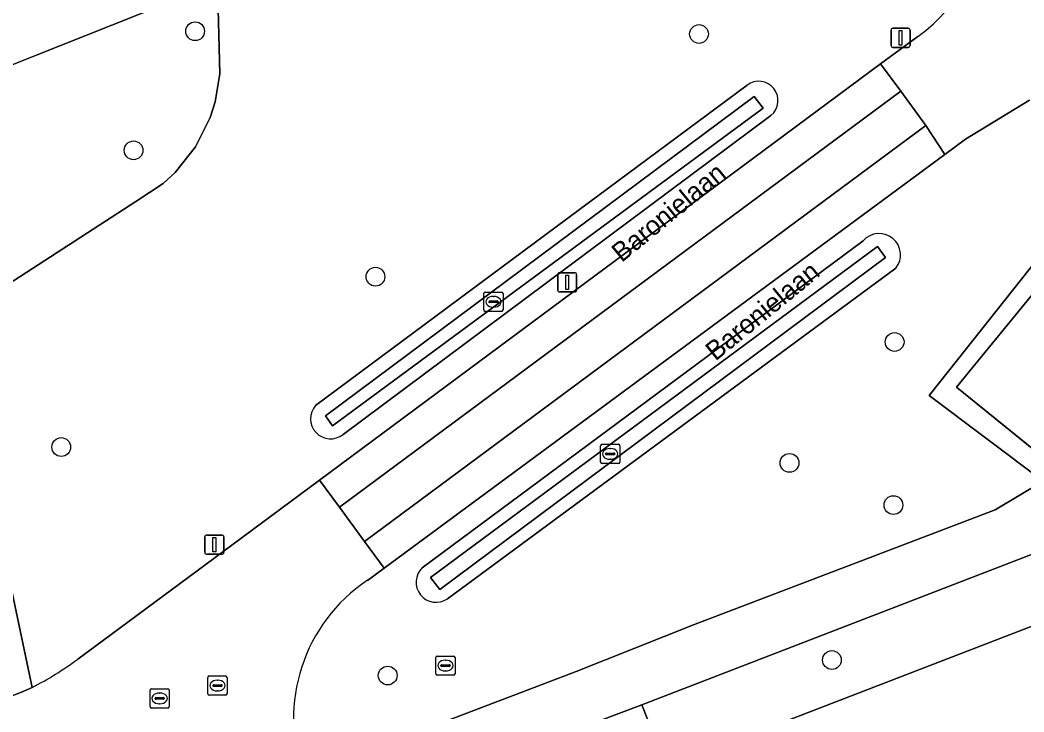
# Model space of a CAD drawing. Extents: x 159680 to 160786, y 387323 to 388340.
# Drawn here: x 160115.9 to 160168.3, y 387981.6 to 388017.7 of the extents above; entities that cross this region are included whole.
import ezdxf

# ---------------------------------------------------------------- set-up
doc = ezdxf.new("R2010")
doc.units = 0
for name, color, linetype in [('IMGEO_Boom', 7, 'Continuous'), ('IMGEO_Greppel_droge_sloot', 7, 'Continuous'), ('IMGEO_Groenvoorziening', 7, 'Continuous'), ('IMGEO_Hek', 7, 'Continuous'), ('IMGEO_Kolk', 7, 'Continuous'), ('IMGEO_Lichtmast', 7, 'Continuous'), ('IMGEO_Oever', 7, 'Continuous'), ('IMGEO_Openbare_ruimte_label', 7, 'Continuous'), ('IMGEO_Rijbaan_lokaal_gesloten', 7, 'Continuous'), ('IMGEO_Rijbaan_lokaal_open', 7, 'Continuous'), ('IMGEO_Rioolput', 7, 'Continuous'), ('IMGEO_Voetpad_halfverhard', 7, 'Continuous'), ('IMGEO_Voetpad_open', 7, 'Continuous')]:
    doc.layers.add(name, color=color, linetype=linetype)

msp = doc.modelspace()

# ---------------------------------------------------------------- linework, layer by layer
at = {"layer": 'IMGEO_Boom'}
for centre in [(160125.059, 388017.13), (160151.34, 388016.988), (160121.849, 388010.923), (160134.465, 388004.336), (160161.542, 388000.932), (160118.077, 387995.456), (160156.06, 387994.63), (160161.48, 387992.432), (160158.273, 387984.354), (160135.103, 387983.546)]:
    msp.add_circle(centre, 0.489, dxfattribs=at)
at = {"layer": 'IMGEO_Greppel_droge_sloot'}
for points in [[(160131.863, 387997.08), (160132.222, 387996.559), (160154.677, 388013.125), (160154.222, 388013.732)], [(160161.064, 388005.344), (160160.652, 388005.915), (160137.331, 387988.662), (160137.818, 387988.027)]]:
    msp.add_lwpolyline(points, close=True, dxfattribs=at)
at = {"layer": 'IMGEO_Groenvoorziening'}
for points in [[(160166.125, 388024.041), (160165.275, 388032.47), (160165.059, 388035.262), (160160.372, 388033.273), (160155.987, 388031.524), (160126.23, 388019.656), (160126.344, 388014.91), (160126.103, 388013.446), (160125.846, 388012.631), (160125.083, 388011.106), (160124.02, 388009.772), (160123.39, 388009.196), (160121.967, 388008.256), (160112.76, 388002.304), (160112.774, 388002.223), (160113.928, 387995.528), (160114.105, 387994.618), (160114.502, 387992.58), (160116.567, 387982.928)], [(160125.846, 388012.631), (160126.103, 388013.446), (160126.344, 388014.91), (160126.23, 388019.656), (160116.649, 388015.835), (160114.456, 388014.96), (160114.154, 388014.758), (160113.722, 388014.469), (160111.987, 388013.468)], [(160160.812, 388015.433), (160162.749, 388016.86)], [(160118.934, 387984.392), (160126.043, 387989.654), (160131.544, 387993.725), (160160.812, 388015.433)], [(160145.042, 388007.789), (160153.852, 388014.325)], [(160168.572, 388013.533), (160165.236, 388011.499), (160164.163, 388010.707), (160134.923, 387989.142), (160134.042, 387988.508)], [(160163.337, 387998.137), (160164.817, 388000), (160172.298, 388009.417), (160179.067, 388004.335), (160179.091, 388004.369), (160181.002, 388007.834), (160181.761, 388009.621), (160182.319, 388011.579), (160183.007, 388013.607)], [(160111.224, 388011.36), (160112.76, 388002.304), (160121.967, 388008.256), (160123.39, 388009.196), (160124.02, 388009.772), (160125.083, 388011.106), (160125.846, 388012.631)], [(160155.092, 388012.741), (160132.773, 387996.111)], [(160131.344, 387997.627), (160145.042, 388007.789)], [(160136.908, 387989.163), (160159.897, 388006.203)], [(160161.613, 388004.778), (160138.215, 387987.548)], [(160207.556, 387953.24), (160205.296, 387988.427), (160196.008, 387988.241), (160194.379, 387994.988), (160200.5, 387996.578), (160204.723, 387997.367), (160204.554, 388000), (160204.497, 388000.886), (160199.753, 388000), (160193.558, 387998.39), (160191.271, 387997.796), (160189.054, 387997.22), (160177.598, 387993.294), (160148.364, 387982.025), (160149.641, 387978.766), (160178.798, 387990.005), (160187.566, 387993.01), (160192.055, 387994.383), (160193.584, 387987.727), (160185.705, 387985.65), (160177.161, 387982.262), (160177.993, 387979.097)], [(160130.712, 387978.33), (160138.132, 387981.171), (160144.936, 387983.757), (160151.053, 387986.18), (160166.782, 387992.187), (160169.286, 387993.671), (160163.337, 387998.137)]]:
    msp.add_lwpolyline(points, dxfattribs=at)
for points in [[(160164.77, 387998.586), (160165.929, 388000), (160169.168, 388003.949), (160172.564, 388008.09), (160177.63, 388003.943), (160174.171, 388000), (160171.033, 387996.424), (160171.901, 387995.677), (160173.796, 387997.437), (160176.416, 388000.66), (160179.067, 388004.335), (160172.298, 388009.417), (160164.817, 388000), (160163.337, 387998.137), (160169.286, 387993.671), (160170.183, 387994.202)], [(160169.168, 388003.949), (160165.929, 388000), (160164.77, 387998.586), (160170.183, 387994.202), (160171.901, 387995.677), (160171.033, 387996.424), (160174.171, 388000)], [(160177.161, 387982.262), (160185.705, 387985.65), (160193.584, 387987.727), (160192.055, 387994.383), (160187.566, 387993.01), (160178.798, 387990.005), (160149.641, 387978.766), (160152.156, 387972.348)]]:
    msp.add_lwpolyline(points, close=True, dxfattribs=at)
for centre, radius, start, end in [((160158.173, 388023.395), 7.978, 304.9987, 4.6421), ((160154.455, 388013.52), 1.006, 309.2647, 126.845), ((160160.736, 388005.468), 1.116, 321.7912, 138.795), ((160132.125, 387996.932), 1.046, 138.3479, 308.2678), ((160137.625, 387988.407), 1.042, 133.495, 304.4706), ((160138.876, 387981.293), 8.685, 123.8192, 199.9471), ((160108.309, 387998.924), 18.002, 297.3035, 306.1705)]:
    msp.add_arc(centre, radius, start, end, dxfattribs=at)
at = {"layer": 'IMGEO_Hek'}
msp.add_lwpolyline([(160170.41, 387994.018), (160164.77, 387998.586), (160165.929, 388000), (160169.168, 388003.949), (160172.564, 388008.09), (160177.63, 388003.943), (160174.171, 388000), (160171.033, 387996.424), (160172.174, 387995.442)], dxfattribs=at)
at = {"layer": 'IMGEO_Kolk'}
for p, q in [((160140.193, 388003.528), (160141.045, 388003.528)), ((160140.118, 388002.602), (160140.118, 388003.454)), ((160140.377, 388003.022), (160140.377, 388003.034)), ((160140.42, 388003.071), (160140.818, 388003.071)), ((160140.606, 388003.308), (160140.631, 388003.308)), ((160140.861, 388003.034), (160140.861, 388003.022)), ((160141.119, 388003.454), (160141.119, 388002.602)), ((160141.045, 388002.528), (160140.193, 388002.528)), ((160140.815, 388002.985), (160140.417, 388002.985)), ((160140.629, 388002.748), (160140.604, 388002.748)), ((160146.206, 387994.673), (160146.206, 387995.525)), ((160146.281, 387995.599), (160147.133, 387995.599)), ((160146.508, 387995.142), (160146.906, 387995.142)), ((160146.694, 387995.379), (160146.719, 387995.379)), ((160147.207, 387995.525), (160147.207, 387994.673)), ((160146.465, 387995.093), (160146.465, 387995.105)), ((160146.903, 387995.056), (160146.505, 387995.056)), ((160146.717, 387994.819), (160146.692, 387994.819)), ((160146.949, 387995.105), (160146.949, 387995.093)), ((160147.133, 387994.599), (160146.281, 387994.599)), ((160137.614, 387983.637), (160137.614, 387984.489)), ((160137.689, 387984.563), (160138.541, 387984.563)), ((160138.102, 387984.343), (160138.127, 387984.343)), ((160138.615, 387984.489), (160138.615, 387983.637)), ((160137.873, 387984.057), (160137.873, 387984.069)), ((160138.311, 387984.02), (160137.913, 387984.02)), ((160137.916, 387984.106), (160138.314, 387984.106)), ((160138.125, 387983.783), (160138.1, 387983.783)), ((160138.357, 387984.069), (160138.357, 387984.057)), ((160138.541, 387983.563), (160137.689, 387983.563))]:
    msp.add_line(p, q, dxfattribs=at)
for points in [[(160140.193, 388003.528), (160141.045, 388003.528)], [(160140.118, 388002.602), (160140.118, 388003.454)], [(160141.119, 388003.454), (160141.119, 388002.602)], [(160141.045, 388002.528), (160140.193, 388002.528)], [(160146.206, 387994.673), (160146.206, 387995.525)], [(160146.281, 387995.599), (160147.133, 387995.599)], [(160147.207, 387995.525), (160147.207, 387994.673)], [(160147.133, 387994.599), (160146.281, 387994.599)], [(160137.614, 387983.637), (160137.614, 387984.489)], [(160137.689, 387984.563), (160138.541, 387984.563)], [(160138.615, 387984.489), (160138.615, 387983.637)], [(160138.541, 387983.563), (160137.689, 387983.563)]]:
    msp.add_lwpolyline(points, dxfattribs=at)
for centre, radius, start, end in [((160140.195, 388003.452), 0.0765, 91.552, 178.448), ((160140.195, 388003.452), 0.0765, 91.552, 178.448), ((160141.043, 388003.452), 0.0765, 1.552, 88.448), ((160141.043, 388003.452), 0.0765, 1.552, 88.448), ((160140.417, 388003.031), 0.0403, 85.8775, 175.7526), ((160140.414, 388003.021), 0.0366, 178.938, 274.7102), ((160140.818, 388003.028), 0.043, 264.8664, 352.4533), ((160140.822, 388003.033), 0.0386, 1.7309, 96.639), ((160140.195, 388002.604), 0.0765, 181.552, 268.448), ((160140.195, 388002.604), 0.0765, 181.552, 268.448), ((160141.043, 388002.604), 0.0765, 271.552, 358.448), ((160141.043, 388002.604), 0.0765, 271.552, 358.448), ((160146.283, 387995.523), 0.0765, 91.552, 178.448), ((160146.283, 387995.523), 0.0765, 91.552, 178.448), ((160146.505, 387995.102), 0.0403, 85.8775, 175.7526), ((160146.91, 387995.104), 0.0386, 1.7309, 96.639), ((160147.131, 387995.523), 0.0765, 1.552, 88.448), ((160147.131, 387995.523), 0.0765, 1.552, 88.448), ((160146.283, 387994.675), 0.0765, 181.552, 268.448), ((160146.283, 387994.675), 0.0765, 181.552, 268.448), ((160146.502, 387995.092), 0.0366, 178.938, 274.7102), ((160146.906, 387995.099), 0.043, 264.8664, 352.4533), ((160147.131, 387994.675), 0.0765, 271.552, 358.448), ((160147.131, 387994.675), 0.0765, 271.552, 358.448), ((160137.691, 387984.487), 0.0765, 91.552, 178.448), ((160137.691, 387984.487), 0.0765, 91.552, 178.448), ((160138.539, 387984.487), 0.0765, 1.552, 88.448), ((160138.539, 387984.487), 0.0765, 1.552, 88.448), ((160137.691, 387983.639), 0.0765, 181.552, 268.448), ((160137.691, 387983.639), 0.0765, 181.552, 268.448), ((160137.913, 387984.066), 0.0403, 85.8775, 175.7526), ((160137.91, 387984.056), 0.0366, 178.938, 274.7102), ((160138.314, 387984.063), 0.043, 264.8664, 352.4533), ((160138.318, 387984.068), 0.0386, 1.7309, 96.639), ((160138.539, 387983.639), 0.0765, 271.552, 358.448), ((160138.539, 387983.639), 0.0765, 271.552, 358.448)]:
    msp.add_arc(centre, radius, start, end, dxfattribs=at)
for centre, major_axis, ratio, start_param, end_param in [((160140.605, 388003.028), (-0.387, 0.002), 0.722429, 4.712389, 7.853982), ((160140.63, 388003.028), (-0.39, 0.002), 0.717154, 1.570796, 4.712389), ((160146.693, 387995.099), (-0.387, 0.002), 0.722429, 4.712389, 7.853982), ((160146.718, 387995.099), (-0.39, 0.002), 0.717154, 1.570796, 4.712389), ((160138.101, 387984.063), (-0.387, 0.002), 0.722429, 4.712389, 7.853982), ((160138.126, 387984.063), (-0.39, 0.002), 0.717154, 1.570796, 4.712389)]:
    msp.add_ellipse(centre, major_axis=major_axis, ratio=ratio, start_param=start_param, end_param=end_param, dxfattribs=at)
at = {"layer": 'IMGEO_Lichtmast'}
for p, q in [((160161.354, 388016.388), (160161.354, 388017.188)), ((160161.354, 388017.188), (160161.354, 388016.388)), ((160161.454, 388017.288), (160162.244, 388017.288)), ((160162.244, 388017.288), (160161.454, 388017.288)), ((160162.344, 388017.188), (160162.344, 388016.388)), ((160162.344, 388016.388), (160162.344, 388017.188)), ((160162.244, 388016.288), (160161.454, 388016.288)), ((160161.454, 388016.288), (160162.244, 388016.288)), ((160143.968, 388003.641), (160143.968, 388004.441)), ((160143.968, 388004.441), (160143.968, 388003.641)), ((160144.068, 388004.541), (160144.858, 388004.541)), ((160144.858, 388004.541), (160144.068, 388004.541)), ((160144.958, 388004.441), (160144.958, 388003.641)), ((160144.958, 388003.641), (160144.958, 388004.441)), ((160144.858, 388003.541), (160144.068, 388003.541)), ((160144.068, 388003.541), (160144.858, 388003.541)), ((160125.566, 387989.968), (160125.566, 387990.768)), ((160125.566, 387990.768), (160125.566, 387989.968)), ((160125.666, 387990.868), (160126.456, 387990.868)), ((160126.456, 387990.868), (160125.666, 387990.868)), ((160126.556, 387990.768), (160126.556, 387989.968)), ((160126.556, 387989.968), (160126.556, 387990.768)), ((160126.456, 387989.868), (160125.666, 387989.868)), ((160125.666, 387989.868), (160126.456, 387989.868))]:
    msp.add_line(p, q, dxfattribs=at)
for points in [[(160161.774, 388017.163), (160161.924, 388017.163), (160161.924, 388016.413), (160161.774, 388016.413), (160161.774, 388017.163)], [(160144.388, 388004.416), (160144.538, 388004.416), (160144.538, 388003.666), (160144.388, 388003.666), (160144.388, 388004.416)], [(160125.986, 387990.743), (160126.136, 387990.743), (160126.136, 387989.993), (160125.986, 387989.993), (160125.986, 387990.743)]]:
    msp.add_lwpolyline(points, dxfattribs=at)
for centre, start, end in [((160161.454, 388017.188), 90, 180), ((160161.454, 388017.188), 90, 180), ((160162.244, 388017.188), 0, 90), ((160162.244, 388017.188), 360, 90), ((160161.454, 388016.388), 180, 270), ((160161.454, 388016.388), 180, 270), ((160162.244, 388016.388), 270, 0), ((160162.244, 388016.388), 270, 0), ((160144.068, 388004.441), 90, 180), ((160144.068, 388004.441), 90, 180), ((160144.858, 388004.441), 0, 90), ((160144.858, 388004.441), 360, 90), ((160144.068, 388003.641), 180, 270), ((160144.068, 388003.641), 180, 270), ((160144.858, 388003.641), 270, 0), ((160144.858, 388003.641), 270, 0), ((160125.666, 387990.768), 90, 180), ((160125.666, 387990.768), 90, 180), ((160126.456, 387990.768), 0, 90), ((160126.456, 387990.768), 360, 90), ((160125.666, 387989.968), 180, 270), ((160125.666, 387989.968), 180, 270), ((160126.456, 387989.968), 270, 0), ((160126.456, 387989.968), 270, 0)]:
    msp.add_arc(centre, 0.1, start, end, dxfattribs=at)
at = {"layer": 'IMGEO_Oever'}
for points in [[(160153.852, 388014.325), (160145.042, 388007.789), (160131.344, 387997.627)], [(160132.773, 387996.111), (160155.092, 388012.741)], [(160159.897, 388006.203), (160136.908, 387989.163)], [(160138.215, 387987.548), (160161.613, 388004.778)]]:
    msp.add_lwpolyline(points, dxfattribs=at)
for points in [[(160131.863, 387997.08), (160154.222, 388013.732), (160154.677, 388013.125), (160132.222, 387996.559)], [(160161.064, 388005.344), (160137.818, 387988.027), (160137.331, 387988.662), (160160.652, 388005.915)]]:
    msp.add_lwpolyline(points, close=True, dxfattribs=at)
for centre, radius, start, end in [((160154.455, 388013.52), 1.006, 309.2647, 126.845), ((160160.736, 388005.468), 1.116, 321.7912, 138.795), ((160132.125, 387996.932), 1.046, 138.3479, 308.2678), ((160137.625, 387988.407), 1.042, 133.495, 304.4706)]:
    msp.add_arc(centre, radius, start, end, dxfattribs=at)
at = {"layer": 'IMGEO_Rijbaan_lokaal_gesloten'}
for points in [[(160161.866, 388014.009), (160160.812, 388015.433), (160131.544, 387993.725), (160132.587, 387992.324)], [(160164.163, 388010.707), (160163.173, 388012.216), (160133.898, 387990.541), (160134.923, 387989.142)]]:
    msp.add_lwpolyline(points, close=True, dxfattribs=at)
at = {"layer": 'IMGEO_Rijbaan_lokaal_open'}
for points in [[(160162.749, 388016.86), (160160.812, 388015.433), (160161.866, 388014.009), (160163.173, 388012.216), (160164.163, 388010.707), (160165.236, 388011.499), (160168.572, 388013.533)], [(160134.042, 387988.508), (160134.923, 387989.142), (160133.898, 387990.541), (160132.587, 387992.324), (160131.544, 387993.725), (160126.043, 387989.654), (160118.934, 387984.392)], [(160116.567, 387982.928), (160116.007, 387982.686), (160114.953, 387982.272), (160114.267, 387981.984), (160113.681, 387981.763), (160114.307, 387980.164), (160115.127, 387978.084), (160115.759, 387976.477), (160116.703, 387976.841)]]:
    msp.add_lwpolyline(points, dxfattribs=at)
msp.add_lwpolyline([(160163.173, 388012.216), (160161.866, 388014.009), (160132.587, 387992.324), (160133.898, 387990.541)], close=True, dxfattribs=at)
for centre, radius, start, end in [((160158.173, 388023.395), 7.978, 304.9987, 4.6421), ((160138.876, 387981.293), 8.685, 123.8192, 199.9471), ((160108.309, 387998.924), 18.002, 297.3035, 306.1705)]:
    msp.add_arc(centre, radius, start, end, dxfattribs=at)
at = {"layer": 'IMGEO_Rioolput'}
for p, q in [((160125.725, 387982.599), (160125.725, 387983.451)), ((160125.8, 387983.525), (160126.652, 387983.525)), ((160126.213, 387983.305), (160126.238, 387983.305)), ((160126.726, 387983.451), (160126.726, 387982.599)), ((160122.708, 387981.927), (160122.708, 387982.779)), ((160122.783, 387982.853), (160123.635, 387982.853)), ((160123.196, 387982.633), (160123.221, 387982.633)), ((160123.709, 387982.779), (160123.709, 387981.927)), ((160125.984, 387983.019), (160125.984, 387983.031)), ((160126.422, 387982.982), (160126.024, 387982.982)), ((160126.027, 387983.068), (160126.425, 387983.068)), ((160126.236, 387982.745), (160126.211, 387982.745)), ((160126.468, 387983.031), (160126.468, 387983.019)), ((160122.967, 387982.347), (160122.967, 387982.359)), ((160123.405, 387982.31), (160123.007, 387982.31)), ((160123.01, 387982.396), (160123.408, 387982.396)), ((160123.219, 387982.073), (160123.194, 387982.073)), ((160123.451, 387982.359), (160123.451, 387982.347)), ((160126.652, 387982.525), (160125.8, 387982.525)), ((160123.635, 387981.853), (160122.783, 387981.853))]:
    msp.add_line(p, q, dxfattribs=at)
for points in [[(160125.725, 387982.599), (160125.725, 387983.451)], [(160125.8, 387983.525), (160126.652, 387983.525)], [(160126.726, 387983.451), (160126.726, 387982.599)], [(160122.708, 387981.927), (160122.708, 387982.779)], [(160122.783, 387982.853), (160123.635, 387982.853)], [(160123.709, 387982.779), (160123.709, 387981.927)], [(160126.652, 387982.525), (160125.8, 387982.525)], [(160123.635, 387981.853), (160122.783, 387981.853)]]:
    msp.add_lwpolyline(points, dxfattribs=at)
for centre, radius, start, end in [((160125.802, 387983.449), 0.0765, 91.552, 178.448), ((160125.802, 387983.449), 0.0765, 91.552, 178.448), ((160126.65, 387983.449), 0.0765, 1.552, 88.448), ((160126.65, 387983.449), 0.0765, 1.552, 88.448), ((160122.785, 387982.777), 0.0765, 91.552, 178.448), ((160122.785, 387982.777), 0.0765, 91.552, 178.448), ((160123.633, 387982.777), 0.0765, 1.552, 88.448), ((160123.633, 387982.777), 0.0765, 1.552, 88.448), ((160125.802, 387982.601), 0.0765, 181.552, 268.448), ((160125.802, 387982.601), 0.0765, 181.552, 268.448), ((160126.024, 387983.028), 0.0403, 85.8775, 175.7526), ((160126.021, 387983.018), 0.0366, 178.938, 274.7102), ((160126.425, 387983.025), 0.043, 264.8664, 352.4533), ((160126.429, 387983.03), 0.0386, 1.7309, 96.639), ((160126.65, 387982.601), 0.0765, 271.552, 358.448), ((160126.65, 387982.601), 0.0765, 271.552, 358.448), ((160123.007, 387982.356), 0.0403, 85.8775, 175.7526), ((160123.004, 387982.346), 0.0366, 178.938, 274.7102), ((160123.408, 387982.353), 0.043, 264.8664, 352.4533), ((160123.412, 387982.358), 0.0386, 1.7309, 96.639), ((160122.785, 387981.929), 0.0765, 181.552, 268.448), ((160122.785, 387981.929), 0.0765, 181.552, 268.448), ((160123.633, 387981.929), 0.0765, 271.552, 358.448), ((160123.633, 387981.929), 0.0765, 271.552, 358.448)]:
    msp.add_arc(centre, radius, start, end, dxfattribs=at)
for centre, major_axis, ratio, start_param, end_param in [((160126.212, 387983.025), (-0.387, 0.002), 0.722429, 4.712389, 7.853982), ((160126.237, 387983.025), (-0.39, 0.002), 0.717154, 1.570796, 4.712389), ((160123.195, 387982.353), (-0.387, 0.002), 0.722429, 4.712389, 7.853982), ((160123.22, 387982.353), (-0.39, 0.002), 0.717154, 1.570796, 4.712389)]:
    msp.add_ellipse(centre, major_axis=major_axis, ratio=ratio, start_param=start_param, end_param=end_param, dxfattribs=at)
at = {"layer": 'IMGEO_Voetpad_halfverhard'}
msp.add_lwpolyline([(160167.999, 387931.913), (160164.121, 387941.81), (160163.813, 387942.595), (160163.17, 387944.237), (160152.156, 387972.348), (160149.641, 387978.766), (160148.364, 387982.025), (160146.101, 387981.164), (160161.804, 387940.861), (160165.633, 387931.034)], dxfattribs=at)
at = {"layer": 'IMGEO_Voetpad_open'}
for points in [[(160111.987, 388013.468), (160113.722, 388014.469), (160114.154, 388014.758), (160114.456, 388014.96), (160116.649, 388015.835), (160126.23, 388019.656), (160155.987, 388031.524), (160154.362, 388034.628)], [(160108.013, 388012.607), (160110.499, 387999.706), (160110.505, 387999.673), (160111.292, 387995.586), (160111.708, 387993.529), (160114.267, 387981.984), (160114.953, 387982.272), (160116.007, 387982.686), (160116.567, 387982.928), (160114.502, 387992.58), (160114.105, 387994.618), (160113.928, 387995.528), (160112.774, 388002.223), (160112.76, 388002.304), (160111.224, 388011.36)], [(160216.805, 388000.906), (160216.494, 388005.84), (160204.957, 388004.014), (160200.856, 388003.748), (160193.458, 388001.432), (160188.175, 388000), (160180.577, 387997.63), (160176.913, 387996.222), (160169.286, 387993.671), (160166.782, 387992.187), (160151.053, 387986.18), (160144.936, 387983.757), (160138.132, 387981.171)], [(160146.101, 387981.164), (160148.364, 387982.025), (160177.598, 387993.294), (160189.054, 387997.22), (160191.271, 387997.796), (160193.558, 387998.39), (160199.753, 388000)]]:
    msp.add_lwpolyline(points, dxfattribs=at)

# ---------------------------------------------------------------- texts
at = {"layer": 'IMGEO_Openbare_ruimte_label'}
for p in [(160147.304, 388005.047), (160152.199, 387999.908)]:
    msp.add_text('Baronielaan', height=1, rotation=39.3216, dxfattribs=at).set_placement(p)

doc.saveas('drawing.dxf')
